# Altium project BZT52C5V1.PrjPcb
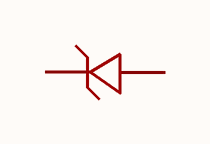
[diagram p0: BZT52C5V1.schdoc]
1 sheet, 1 parts. Net scope: global (net labels, ports and power ports of the same name join across sheets).

## Sheet BZT52C5V1.schdoc
size 127 x 101 mm

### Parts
ZD?  bzt52c5v1_c2117  [SOD-123_L2.8-W1.8-LS3.7-RD]  (value not drawn)

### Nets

Not connected (* = marked no-connect by the designer): ZD? 1(K) 2(A)

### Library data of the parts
ZD? = bzt52c5v1_c2117: 二极管配置:1个独立式;稳压值(标称值):5.1V;稳压值(范围):4.8V~5.4V;耗散功率(Pd):500mW;; Manufacturer: CJ(江苏长电/长晶); AddInBom: yes; ModelId: 7884390a25fb4c08947731ebfba7e3f8; ModelTransform: 144.8816,62.992,0,0,0,0,0,0,0; Diode Configuration: 1个独立式; Zener Voltage(Nom): 5.1V; Reverse Leakage Current (Ir): 2uA; Pd - Power Dissipation: 500mW; Impedance(Zzt): 60Ω; Impedance(Zzk): 480Ω; Operating Junction Temperature Range: -55℃~+150℃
